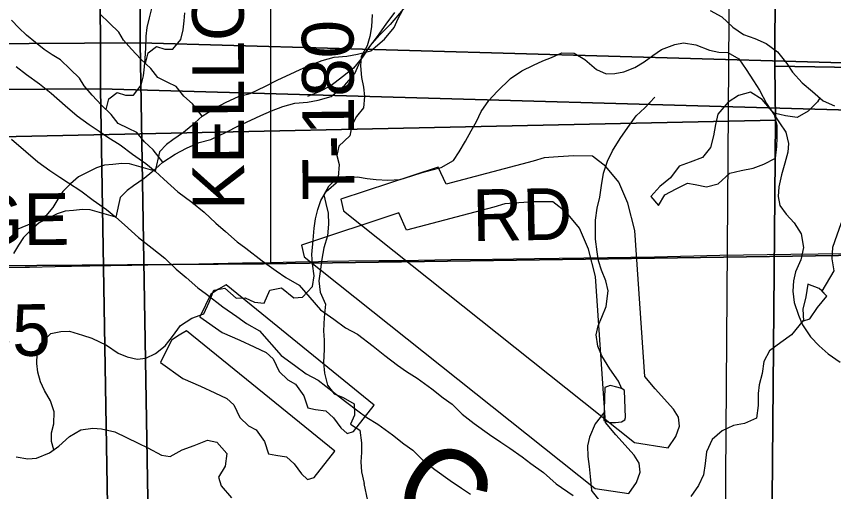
# Model space of a CAD drawing. Extents: x -21.1 to 50.3, y 0 to 22.1.
# Drawn here: x 3.669 to 4.567, y 17.521 to 18.044 of the extents above; entities that cross this region are included whole.
import ezdxf

# ---------------------------------------------------------------- set-up
doc = ezdxf.new("R2010")
doc.units = 0
for name, color, linetype in [('GM_X_County_Road', 7, 'Continuous'), ('GM_X_County_Road_Text', 7, 'Continuous'), ('GM_X_Major_River', 7, 'Continuous'), ('GM_X_Major_River_Text', 7, 'Continuous'), ('GM_X_Minor_Lake', 7, 'Continuous'), ('GM_X_Minor_River', 7, 'Continuous'), ('GM_X_Section', 7, 'Continuous'), ('GM_X_State_Route', 7, 'Continuous'), ('GM_X_Township_Road', 7, 'Continuous'), ('GM_X_Township_Road_Text', 7, 'Continuous')]:
    doc.layers.add(name, color=color, linetype=linetype)

msp = doc.modelspace()

# ---------------------------------------------------------------- linework, layer by layer
at = {"layer": 'GM_X_County_Road'}
msp.add_lwpolyline([(3.62878, 17.7673), (3.67832, 17.76822), (3.68307, 17.76831), (3.7113, 17.76885), (3.72919, 17.7692), (3.74939, 17.76959), (3.79552, 17.77048), (3.83088, 17.77116), (3.84615, 17.77146), (3.86907, 17.7719), (3.90137, 17.77253), (3.9171, 17.77284), (3.94848, 17.77344), (3.97527, 17.77392), (4.00059, 17.77437), (4.01052, 17.77454), (4.03394, 17.77497), (4.0673, 17.77556), (4.09291, 17.77561), (4.14607, 17.77644), (4.19183, 17.77689), (4.23824, 17.7776), (4.2923, 17.77837), (4.37021, 17.77959), (4.44181, 17.7812), (4.51972, 17.78229), (4.58014, 17.78332)], dxfattribs=at)
at = {"layer": 'GM_X_Major_River'}
for points in [[(3.6685, 17.98853), (3.67957, 17.97989), (3.69407, 17.96976), (3.70668, 17.95923), (3.72234, 17.9457), (3.73534, 17.93442), (3.74869, 17.92504), (3.75976, 17.91754), (3.76929, 17.91116), (3.78265, 17.90254), (3.79639, 17.89241), (3.81089, 17.8819), (3.8212, 17.87363), (3.83076, 17.86498), (3.84605, 17.85106), (3.86132, 17.83942), (3.87506, 17.82853), (3.88768, 17.81648), (3.89838, 17.80746), (3.91137, 17.7958), (3.92092, 17.78905), (3.93886, 17.77515), (3.95413, 17.76427), (3.96481, 17.75677), (3.9793, 17.74853), (4.00304, 17.7214), (4.01754, 17.71089), (4.03052, 17.70151), (4.04348, 17.6944), (4.06066, 17.68126), (4.07364, 17.67112), (4.08739, 17.6606), (4.09731, 17.65347), (4.10913, 17.64598), (4.12516, 17.63434), (4.13776, 17.62458), (4.14768, 17.61745), (4.15878, 17.60653), (4.17176, 17.59639), (4.18855, 17.58438), (4.20114, 17.57575), (4.21106, 17.56938), (4.22442, 17.55962), (4.23396, 17.55249), (4.24808, 17.54235), (4.26184, 17.52994), (4.28054, 17.51719)], [(3.66339, 17.90872), (3.67906, 17.89518), (3.69205, 17.8839), (3.7054, 17.87452), (3.71647, 17.86702), (3.726, 17.86065), (3.73936, 17.85203), (3.7531, 17.84189), (3.7676, 17.83138), (3.77791, 17.82311), (3.78747, 17.81447), (3.80276, 17.80055), (3.81803, 17.7889), (3.83177, 17.77801), (3.84439, 17.76597), (3.85509, 17.75695), (3.86809, 17.74529), (3.87763, 17.73853), (3.89557, 17.72464), (3.91084, 17.71375), (3.92152, 17.70625), (3.93601, 17.69802), (3.95975, 17.67089), (3.97425, 17.66038), (3.98723, 17.65099), (4.00019, 17.64389), (4.01737, 17.63074), (4.03035, 17.6206), (4.0441, 17.61009), (4.05402, 17.60296), (4.06584, 17.59546), (4.08187, 17.58383), (4.09447, 17.57406), (4.1044, 17.56693), (4.11549, 17.55601), (4.12847, 17.54587), (4.14526, 17.53386), (4.15785, 17.52524), (4.16777, 17.51886)]]:
    msp.add_lwpolyline(points, dxfattribs=at)
at = {"layer": 'GM_X_Minor_Lake'}
for points in [[(4.50167, 17.93724), (4.49867, 17.94023), (4.48838, 17.95239), (4.47543, 17.96036), (4.4625, 17.95692), (4.45109, 17.9493), (4.4397, 17.93635), (4.43705, 17.92494), (4.43478, 17.91239), (4.43176, 17.89946), (4.42264, 17.8888), (4.40933, 17.88346), (4.39716, 17.87926), (4.38767, 17.86632), (4.37589, 17.8568), (4.36601, 17.84576), (4.3744, 17.83588), (4.38123, 17.84768), (4.39378, 17.85416), (4.40632, 17.86026)], [(4.50171, 17.93719), (4.49867, 17.94023), (4.48838, 17.95239), (4.47543, 17.96036), (4.4625, 17.95692), (4.45109, 17.9493), (4.4397, 17.93635), (4.43705, 17.92494), (4.43478, 17.91239), (4.43176, 17.89946), (4.42264, 17.8888), (4.40933, 17.88346), (4.39716, 17.87926), (4.38767, 17.86632), (4.37589, 17.8568), (4.36601, 17.84576), (4.3744, 17.83588), (4.38123, 17.84768), (4.39378, 17.85416), (4.40632, 17.86026)], [(4.40632, 17.86026), (4.4147, 17.85913), (4.42726, 17.85648), (4.44019, 17.85954), (4.45273, 17.87134), (4.46528, 17.8744), (4.47859, 17.87708), (4.49038, 17.88128), (4.50293, 17.88776), (4.50443, 17.90069), (4.5048, 17.9102), (4.50478, 17.92389), (4.50167, 17.93724)], [(4.40632, 17.86026), (4.4147, 17.85913), (4.42726, 17.85648), (4.44019, 17.85954), (4.45273, 17.87134), (4.46528, 17.8744), (4.47859, 17.87708), (4.49038, 17.88128), (4.50293, 17.88776), (4.50443, 17.90069), (4.5048, 17.9102), (4.50478, 17.92389), (4.50168, 17.9372)], [(4.02541, 17.84289), (4.02821, 17.83002), (4.3481, 17.57543), (4.38495, 17.56975), (4.39354, 17.58199), (4.39758, 17.59341), (4.39633, 17.60327), (4.39093, 17.61194), (4.37095, 17.63449), (4.35943, 17.64802), (4.34853, 17.80841), (4.34061, 17.83831), (4.33086, 17.86135), (4.31664, 17.87865), (4.30172, 17.89025), (4.28124, 17.89041), (4.26418, 17.88947), (4.24865, 17.88816), (4.23655, 17.88462), (4.14089, 17.85931), (4.13234, 17.87819)], [(4.13234, 17.87819), (4.02541, 17.84289)], [(3.98212, 17.79237), (3.98492, 17.7795), (4.30481, 17.52491), (4.34167, 17.51924), (4.35025, 17.53147), (4.35429, 17.5429), (4.35304, 17.55275), (4.34764, 17.56142), (4.32767, 17.58397), (4.31614, 17.59751), (4.30524, 17.7579), (4.29732, 17.78779), (4.28758, 17.81083), (4.27335, 17.82813), (4.25843, 17.83974), (4.23795, 17.8399), (4.2209, 17.83895), (4.20536, 17.83765), (4.19326, 17.8341), (4.0976, 17.80879), (4.08905, 17.82767)], [(4.08905, 17.82767), (3.98212, 17.79237)], [(3.89904, 17.74857), (3.89075, 17.74393), (3.88247, 17.73852), (3.87023, 17.71373), (3.8947, 17.69616), (3.91413, 17.68802), (3.93014, 17.6806), (3.94311, 17.67429), (3.95077, 17.66754), (3.95737, 17.65357), (3.96696, 17.64419), (3.97535, 17.63973), (3.9846, 17.62692), (3.98892, 17.61369), (3.99728, 17.61188), (4.00868, 17.61011), (4.0171, 17.60261), (4.02519, 17.59169), (4.03209, 17.58532), (4.03927, 17.58767), (4.06208, 17.61637)], [(4.06208, 17.61637), (3.89904, 17.74857)], [(4.55407, 17.74215), (4.55108, 17.74484), (4.53852, 17.74939), (4.53626, 17.7357), (4.53324, 17.722), (4.53364, 17.70908)], [(4.53364, 17.70908), (4.54086, 17.71137), (4.54921, 17.72393), (4.55947, 17.73611), (4.55407, 17.74215)], [(4.53364, 17.70908), (4.54086, 17.71137), (4.54921, 17.72393), (4.55947, 17.73611), (4.55407, 17.74181)], [(3.85575, 17.69805), (3.84746, 17.69341), (3.83918, 17.68801), (3.82694, 17.66321), (3.85141, 17.64564), (3.87084, 17.6375), (3.88685, 17.63008), (3.89982, 17.62377), (3.90748, 17.61703), (3.91408, 17.60306), (3.92367, 17.59367), (3.93206, 17.58921), (3.94131, 17.57641), (3.94563, 17.56317), (3.95399, 17.56137), (3.96539, 17.55959), (3.97381, 17.55209), (3.9819, 17.54118), (3.9888, 17.5348), (3.99598, 17.53715), (4.01879, 17.56586)], [(4.01879, 17.56586), (3.85575, 17.69805)], [(4.31424, 17.59982), (4.32106, 17.59755), (4.32712, 17.59755), (4.33394, 17.59831), (4.33736, 17.60021), (4.33812, 17.60286), (4.337, 17.63244), (4.33396, 17.63472), (4.32714, 17.63661), (4.32146, 17.63813), (4.31539, 17.63585)], [(4.31539, 17.63585), (4.31424, 17.59982)]]:
    msp.add_lwpolyline(points, dxfattribs=at)
at = {"layer": 'GM_X_Minor_River'}
for points in [[(4.10011, 18.05914), (4.0796, 18.03477), (4.0682, 18.02335), (4.05681, 18.01078), (4.04921, 17.99899), (4.03934, 17.9868), (4.02718, 17.97728), (4.01425, 17.96738), (4.00133, 17.9609), (3.98878, 17.95556)], [(3.76716, 17.94142), (3.77022, 17.95295), (3.77931, 17.96022), (3.78847, 17.95723), (3.79722, 17.95728), (3.80592, 17.96796), (3.80852, 17.97823), (3.80961, 17.98812), (3.81032, 17.99724), (3.81102, 18.00864), (3.81132, 18.02193), (3.81241, 18.03144), (3.81502, 18.04209), (3.81799, 18.05388)], [(3.87281, 17.93391), (3.88662, 17.94271), (3.89907, 17.9493), (3.91265, 17.95551), (3.9255, 17.95907), (3.94248, 17.96684), (3.95606, 17.97381), (3.96964, 17.98003), (3.98057, 17.98546), (3.99227, 17.99052), (4.00474, 17.99521), (4.01797, 17.99876), (4.03199, 18.00005), (4.04372, 18.00208), (4.05809, 18.00602), (4.07311, 18.01871), (4.08397, 18.03134), (4.08841, 18.04126), (4.09323, 18.0508)], [(4.43116, 18.05005), (4.4441, 18.04322), (4.4563, 18.03182), (4.46772, 18.02385), (4.48029, 18.01931), (4.49285, 18.014), (4.50542, 18.00489), (4.51533, 17.99197), (4.52181, 17.98247), (4.53249, 17.9707), (4.54353, 17.9612), (4.55535, 17.95095), (4.56791, 17.94526)], [(3.82952, 17.88339), (3.81888, 17.897), (3.80931, 17.90568), (3.80088, 17.91627), (3.79172, 17.9204), (3.78065, 17.92604), (3.77298, 17.93587), (3.76227, 17.94607), (3.75193, 17.95703), (3.74311, 17.96723), (3.73812, 17.97594), (3.72778, 17.98576), (3.71707, 17.99596), (3.7079, 18.00161), (3.69911, 18.00725), (3.68955, 18.01518), (3.67961, 18.0231), (3.67119, 18.03103), (3.66315, 18.03972)], [(3.87281, 17.93391), (3.86217, 17.94752), (3.8526, 17.9562), (3.84417, 17.96679), (3.83501, 17.97091), (3.82394, 17.97655), (3.81627, 17.98639), (3.80555, 17.99658), (3.79522, 18.00754), (3.7864, 18.01775), (3.78141, 18.02646), (3.77107, 18.03628), (3.76036, 18.04648)], [(3.81044, 17.99193), (3.81351, 18.00347), (3.8226, 18.01073), (3.83176, 18.00775), (3.84051, 18.00779), (3.84921, 18.01848), (3.85181, 18.02875), (3.8529, 18.03863), (3.85361, 18.04775)], [(3.82952, 17.88339), (3.84334, 17.8922), (3.85578, 17.89878), (3.86936, 17.905), (3.88221, 17.90855), (3.89919, 17.91632), (3.91277, 17.9233), (3.92635, 17.92952), (3.93728, 17.93494), (3.94899, 17.94), (3.96145, 17.94469), (3.97468, 17.94825), (3.9887, 17.94954), (4.00043, 17.95156), (4.0148, 17.95551), (4.02983, 17.96819), (4.04068, 17.98083), (4.04512, 17.99074), (4.04995, 18.00028), (4.05704, 18.0106), (4.06563, 18.0217), (4.07496, 18.03508), (4.08468, 18.04808)], [(4.05974, 18.04581), (4.05897, 18.03216), (4.05707, 18.02154), (4.05403, 18.0113), (4.04758, 17.99954), (4.04682, 17.9893), (4.04795, 17.9764), (4.05022, 17.96578), (4.05135, 17.95554), (4.05021, 17.94303), (4.04262, 17.93355), (4.03731, 17.92368), (4.03503, 17.9123), (4.02289, 17.90093), (4.02099, 17.89069), (4.02326, 17.88083), (4.0225, 17.86717), (4.01188, 17.85693), (4.00657, 17.84745), (4.00884, 17.83797), (4.01148, 17.82735), (4.01186, 17.81521), (4.01071, 17.80269), (4.00654, 17.78942), (4.00426, 17.7769), (4.00273, 17.7659), (4.00121, 17.75301), (4.00272, 17.74049), (4.0084, 17.7276), (4.00688, 17.71281), (4.00611, 17.69802), (4.00686, 17.68777), (4.00686, 17.67753), (4.00609, 17.6635), (4.00722, 17.65175), (4.01063, 17.63847), (4.01783, 17.62899), (4.02768, 17.62482), (4.03981, 17.61799), (4.04018, 17.60548), (4.036, 17.59562), (4.04623, 17.58917), (4.04812, 17.57514), (4.04812, 17.56452), (4.04735, 17.55428), (4.04811, 17.54328), (4.05075, 17.53038)], [(3.70961, 17.56731), (3.70716, 17.57655), (3.7073, 17.58605), (3.70974, 17.59589), (3.71032, 17.60918), (3.70595, 17.6214), (3.69967, 17.63251), (3.69526, 17.64208), (3.69238, 17.65276), (3.69101, 17.66227), (3.69156, 17.6729), (3.69476, 17.68349), (3.70633, 17.69509), (3.71739, 17.69758), (3.72689, 17.69782), (3.74125, 17.69342), (3.75146, 17.69023), (3.76767, 17.68239), (3.78044, 17.67346), (3.79026, 17.66951), (3.80123, 17.66706), (3.81074, 17.66806), (3.82146, 17.67321), (3.83223, 17.68179), (3.84036, 17.69192), (3.8489, 17.70395), (3.86156, 17.71211), (3.87455, 17.71686), (3.88045, 17.72968), (3.88559, 17.7429), (3.89778, 17.74499), (3.91014, 17.73417), (3.92002, 17.7344), (3.9302, 17.72969), (3.94082, 17.72839), (3.94712, 17.74273), (3.96008, 17.74557), (3.97358, 17.73435), (3.98309, 17.73534), (3.99428, 17.74695), (3.99598, 17.7587), (3.99428, 17.77164), (3.9933, 17.78192), (3.99469, 17.79785), (3.99603, 17.81112), (3.99733, 17.82136), (4.00015, 17.83158), (4.00334, 17.8414), (4.00919, 17.85119), (4.02267, 17.86315), (4.03298, 17.86679), (4.04362, 17.86739), (4.05423, 17.86571), (4.06409, 17.86442), (4.07699, 17.86384), (4.0903, 17.8644), (4.10327, 17.86838), (4.11472, 17.87201), (4.12426, 17.8749), (4.1357, 17.87777), (4.14911, 17.88516), (4.15534, 17.89495), (4.16235, 17.90662), (4.16861, 17.91792), (4.17446, 17.92809), (4.17957, 17.93902), (4.18812, 17.95143), (4.197, 17.96118), (4.21166, 17.97539), (4.22432, 17.98393), (4.23695, 17.9902), (4.24728, 17.99498), (4.25684, 17.99864), (4.26831, 18.00378), (4.28159, 18.0032), (4.29364, 17.99618), (4.30639, 17.98535), (4.31695, 17.98063), (4.32645, 17.98086), (4.33635, 17.98261), (4.34858, 17.98737), (4.35855, 17.99367), (4.36816, 18.00075), (4.37775, 18.00744), (4.39227, 18.01292), (4.40179, 18.01467), (4.41544, 18.01257), (4.43054, 18.00664), (4.44075, 18.0042), (4.45063, 18.00405), (4.46267, 17.99704), (4.47085, 17.98551), (4.47901, 17.97285), (4.48531, 17.9625), (4.49306, 17.94795), (4.50011, 17.93758), (4.50755, 17.92683), (4.51422, 17.91647), (4.51745, 17.90389), (4.51654, 17.89441), (4.51331, 17.8823)], [(4.33429, 17.63447), (4.33056, 17.64268), (4.32109, 17.65633), (4.312, 17.67075), (4.30783, 17.68137), (4.30594, 17.69388), (4.30822, 17.70374), (4.31202, 17.71322), (4.31695, 17.72498), (4.31924, 17.74205), (4.31659, 17.75305), (4.31167, 17.7648), (4.30864, 17.77504), (4.30713, 17.7849), (4.30524, 17.79894), (4.30525, 17.80918), (4.30525, 17.8198), (4.30715, 17.83307), (4.30981, 17.84521), (4.31172, 17.85772), (4.314, 17.87138), (4.31855, 17.88465), (4.32387, 17.89603), (4.33221, 17.90969), (4.34056, 17.92144), (4.35004, 17.93434), (4.35952, 17.94307), (4.37052, 17.95482)], [(4.55161, 17.95419), (4.54926, 17.9498), (4.539, 17.93952), (4.52684, 17.93266), (4.5139, 17.93455), (4.50171, 17.93719)], [(3.87281, 17.93391), (3.86068, 17.92308), (3.85241, 17.91616), (3.84075, 17.90807), (3.83359, 17.90306), (3.8261, 17.89501), (3.8212, 17.87363)], [(4.61608, 17.90782), (4.61477, 17.90387), (4.61669, 17.89019), (4.61291, 17.87801), (4.60455, 17.86545), (4.59544, 17.85327), (4.58443, 17.83919), (4.5795, 17.82701), (4.57495, 17.8156), (4.5704, 17.80343), (4.56586, 17.78973), (4.56511, 17.77718), (4.56704, 17.76425), (4.55407, 17.74181)], [(3.8212, 17.87363), (3.79288, 17.88179), (3.7845, 17.88212), (3.77461, 17.88093), (3.76548, 17.88012), (3.75674, 17.87741), (3.73701, 17.86742), (3.72829, 17.85978), (3.71958, 17.85137), (3.7143, 17.84298), (3.70865, 17.83384), (3.70108, 17.82468), (3.69274, 17.81893), (3.68097, 17.81431), (3.66844, 17.8093)], [(3.82952, 17.88339), (3.81739, 17.87257), (3.80912, 17.86565), (3.79746, 17.85755), (3.79031, 17.85254), (3.78281, 17.8445), (3.77791, 17.82311)], [(4.51331, 17.8823), (4.50969, 17.86944), (4.50684, 17.85656), (4.50591, 17.84594), (4.50766, 17.83604), (4.51473, 17.82643), (4.52369, 17.8168), (4.5311, 17.80491), (4.53391, 17.78967), (4.53104, 17.77604), (4.52513, 17.76283), (4.5227, 17.75299), (4.52215, 17.7416), (4.52348, 17.72943), (4.5282, 17.7153), (4.53259, 17.7046), (4.5415, 17.69154), (4.55122, 17.68152), (4.56097, 17.67301), (4.57411, 17.6637)], [(3.77791, 17.82311), (3.74959, 17.83127), (3.74121, 17.83161), (3.73132, 17.83041), (3.72219, 17.8296), (3.71345, 17.8269), (3.69372, 17.81691), (3.68501, 17.80926), (3.6763, 17.80086), (3.67102, 17.79247), (3.66536, 17.78332)], [(4.53352, 17.70935), (4.52072, 17.69385), (4.50894, 17.68547), (4.49639, 17.67633), (4.49032, 17.66453), (4.48844, 17.65122), (4.48503, 17.63867), (4.48391, 17.62916), (4.48393, 17.61623), (4.48205, 17.60216), (4.46912, 17.59644), (4.45694, 17.59414), (4.4444, 17.58842), (4.43338, 17.5789), (4.42731, 17.56521), (4.42581, 17.55228), (4.42392, 17.5401), (4.41823, 17.52831), (4.40988, 17.51613)], [(4.3145, 17.6082), (4.30475, 17.59603), (4.29868, 17.58124), (4.2964, 17.57176), (4.29678, 17.56), (4.29829, 17.549), (4.29942, 17.538), (4.30093, 17.52321)], [(3.66853, 17.55967), (3.68103, 17.55758), (3.69092, 17.55819), (3.70506, 17.56405), (3.71543, 17.57149), (3.72699, 17.58195), (3.73964, 17.58936), (3.75258, 17.59106), (3.76207, 17.59054), (3.77683, 17.58728), (3.80246, 17.57473), (3.81302, 17.56963), (3.82808, 17.56143), (3.83756, 17.56014), (3.85097, 17.56754), (3.86395, 17.57228), (3.87886, 17.57813), (3.88908, 17.5757), (3.8999, 17.56338), (3.89816, 17.54935), (3.89076, 17.5373), (3.89365, 17.52776), (3.90522, 17.51467)], [(4.05477, 17.51149), (4.05075, 17.53038)], [(4.31391, 17.5061), (4.30093, 17.52321)]]:
    msp.add_lwpolyline(points, dxfattribs=at)
at = {"layer": 'GM_X_Section'}
for points in [[(2.75941, 19.00342), (3.80166, 19.0044), (3.80452, 18.01477), (2.7666, 18.00853)], [(3.83539, 19.00471), (4.83075, 19.0046), (4.83425, 17.98542), (3.80452, 18.01477), (3.80166, 19.0044)], [(5.47114, 18.99721), (5.48815, 17.97251), (4.50247, 17.98887), (4.50596, 18.94006), (4.50668, 19.00183)], [(2.71612, 18.9529), (3.75837, 18.95389), (3.76124, 17.96425), (2.72331, 17.95801)], [(3.7921, 18.95419), (4.78746, 18.95409), (4.79096, 17.9349), (3.76124, 17.96425), (3.75837, 18.95389)], [(4.50596, 18.94006), (4.50247, 17.98887), (4.50289, 17.92975), (3.48086, 17.90781), (3.48506, 18.92038)], [(4.45293, 18.14262), (5.45742, 18.14589), (5.45266, 17.13084), (4.44556, 17.13365)], [(2.7666, 18.00853), (3.80452, 18.01477), (3.82173, 16.99041), (2.77975, 16.9773), (2.7786, 17.02922), (2.76737, 17.95698)], [(3.80452, 18.01477), (4.83425, 17.98542), (4.84683, 16.96859), (4.43354, 16.98495), (3.82173, 16.99041)], [(4.50247, 17.98887), (5.48815, 17.97251), (5.52017, 16.94387), (4.49435, 16.93023), (4.50289, 17.92975)], [(2.72331, 17.95801), (3.76124, 17.96425), (3.77844, 16.93989), (2.73646, 16.92678), (2.73531, 16.9787), (2.72408, 17.90647)], [(3.76124, 17.96425), (4.79096, 17.9349), (4.80354, 16.91807), (4.39025, 16.93443), (3.77844, 16.93989)], [(3.48086, 17.90781), (4.50289, 17.92975), (4.49435, 16.93023), (4.49436, 16.90218), (3.4856, 16.89423)]]:
    msp.add_lwpolyline(points, close=True, dxfattribs=at)
at = {"layer": 'GM_X_State_Route'}
msp.add_lwpolyline([(6.52955, 20.9), (2.1, 20.9), (2.1, 17.74017), (2.42851, 17.74626), (2.73209, 17.75291), (3.03298, 17.75833), (3.3026, 17.76263), (3.44154, 17.76826), (3.94025, 17.77171), (5.33072, 17.79178), (6.52196, 17.81036), (6.52225, 18.35692), (6.52255, 18.97782), (6.52273, 19.34666), (6.52977, 20.39859)], close=True, dxfattribs=at)
msp.add_lwpolyline([(6.51283, 14.60317), (6.5142, 14.9441), (6.51464, 15.03489), (6.514, 15.09364), (6.51465, 15.30312), (6.51595, 15.49226), (6.51982, 16.08256), (6.52123, 16.24517), (6.52315, 16.46813), (6.52222, 16.85672), (6.52013, 17.69645), (6.52053, 17.72081), (6.52196, 17.81036), (5.33072, 17.79178), (3.94025, 17.77171), (3.44154, 17.76826), (3.3026, 17.76263), (3.03298, 17.75833), (2.73209, 17.75291), (2.42851, 17.74626), (2.1, 17.74017), (2.1, 14.1)], dxfattribs=at)
at = {"layer": 'GM_X_Township_Road'}
msp.add_lwpolyline([(3.94848, 17.77344), (3.9484, 17.82506), (3.94806, 18.3195), (3.94822, 18.4394), (3.94758, 18.488), (3.94727, 18.5529), (3.94791, 18.74202), (3.94774, 18.79957), (3.94743, 18.84034), (3.94727, 18.86719), (3.94694, 18.91148), (3.9471, 18.95256), (3.94694, 18.96711), (3.94663, 18.99588), (3.94651, 19.01379), (3.9463, 19.03394), (3.9461, 19.06211), (3.94589, 19.08134), (3.94548, 19.12094)], dxfattribs=at)

# ---------------------------------------------------------------- texts
at = {"layer": 'GM_X_County_Road_Text'}
for s, rotation, p in [('RD', 0.98721, (4.17026, 17.79665)), ('LEDGE', 0.41951, (3.46964, 17.79083)), ('C-135', 0.27531, (3.49945, 17.66976))]:
    msp.add_text(s, height=0.056818, rotation=rotation, dxfattribs=at).set_placement(p)
at = {"layer": 'GM_X_Major_River_Text'}
msp.add_text('Creek', height=0.094722, rotation=326.46466, dxfattribs=at).set_placement((4.07411, 17.50773))
at = {"layer": 'GM_X_Township_Road_Text'}
for s, rotation, p in [('KELLOGG', 90.14628, (3.91912, 17.83091)), ('T-180', 90.28178, (4.04009, 17.84146))]:
    msp.add_text(s, height=0.056818, rotation=rotation, dxfattribs=at).set_placement(p)

doc.saveas('drawing.dxf')
